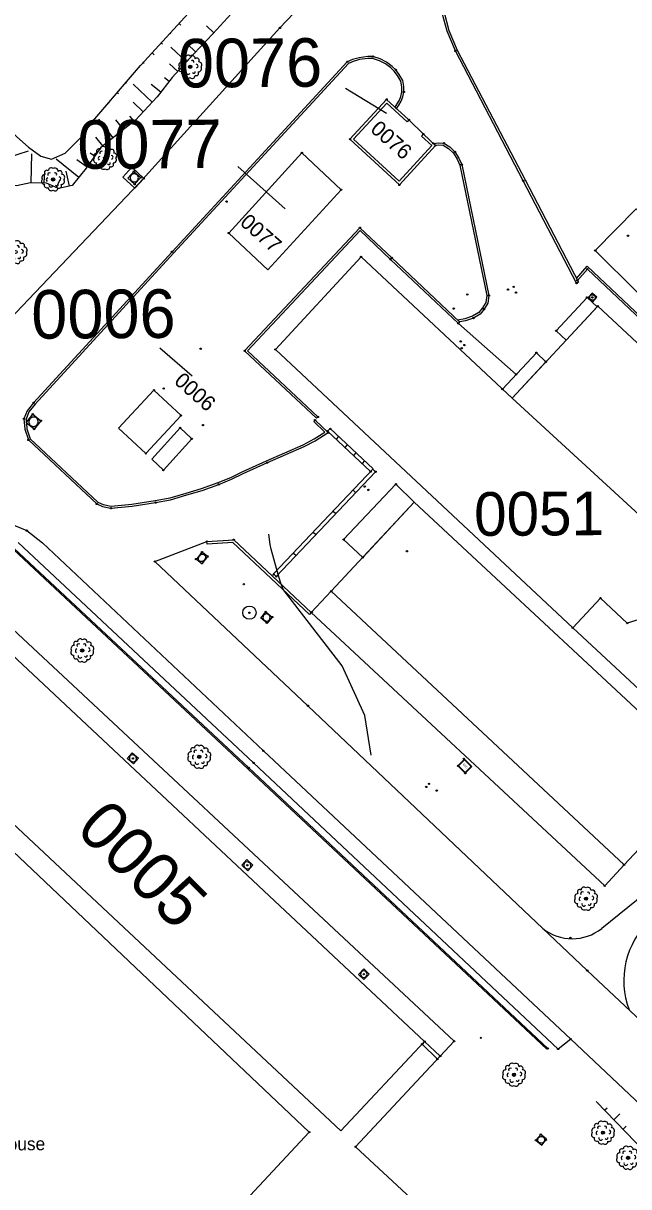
# Model space of a CAD drawing. Extents: x 344013 to 344423, y 298505 to 298795.
# Drawn here: x 344176.7 to 344222.4, y 298618.3 to 298706.1 of the extents above; entities that cross this region are included whole.
import ezdxf

# ---------------------------------------------------------------- set-up
doc = ezdxf.new("R2010")
doc.units = 0
for name, color, linetype in [('Default', 7, 'Continuous'), ('DH_CADRE -CARTOUCHE', 7, 'Continuous'), ('GO_MUR', 7, 'Continuous'), ('PC_CONCRETE', 7, 'Continuous'), ('PS_BOLT', 7, 'Continuous'), ('PS_CONST', 7, 'Continuous'), ('PS_HIDDEN', 7, 'Continuous'), ('PS_SOLID', 7, 'Continuous'), ('RES_ELECTRICITE', 7, 'Continuous'), ('TOPO_POINT', 7, 'Continuous'), ('TOPO_TALUS-TERRAIN NATUREL', 7, 'Continuous'), ('VOIRIE_BORDURE', 7, 'Continuous'), ('VOIRIE_ESPACE VERT', 7, 'Continuous')]:
    doc.layers.add(name, color=color, linetype=linetype)

# ---------------------------------------------------------------- blocks, each defined once
blk = doc.blocks.new('REG_INC')
at = {"layer": 'Default'}
for p, q in [((0, 1), (1, 1)), ((0, 0), (0, 1)), ((1, 0), (0, 0)), ((1, 1), (1, 0))]:
    blk.add_line(p, q, dxfattribs=at)
for start, end in [(135.0055, 180.0055), (180.0066, 225.0066), (90.0058, 135.0058), (225.0069, 270.0069), (45.0069, 90.0069), (270.0058, 315.0058), (0.0066, 45.0066), (315.0055, 0.0055)]:
    blk.add_arc((0.5, 0.5), 0.44, start, end, dxfattribs=at)
blk = doc.blocks.new('R5')
at = {"layer": 'Default'}
for p, q in [((0, 1), (0, 0)), ((1, 1), (0, 1)), ((0.2, 1), (0.2, 0)), ((0.4, 1), (0.4, 0)), ((0.6, 1), (0.6, 0)), ((0.8, 1), (0.8, 0)), ((1, 0), (1, 1)), ((0, 0), (1, 0)), ((0.6, 0), (0.6, 0))]:
    blk.add_line(p, q, dxfattribs=at)
blk = doc.blocks.new('RES_ELECTRICITE')
at = {"layer": 'RES_ELECTRICITE'}
for points in [[(0, 0), (0, 1), (1, 1), (1, 0)], [(0.05, 0.05), (0.05, 0.95), (0.95, 0.95), (0.95, 0.05)]]:
    blk.add_lwpolyline(points, close=True, dxfattribs=at)
blk.add_text('EEC', height=0.2, dxfattribs=at).set_placement((0.24, 0.46))
blk = doc.blocks.new('POINT_DISPLAY')
at = {"layer": 'Default'}
blk.add_circle((0, 0), 0.05, dxfattribs=at)
blk = doc.blocks.new('ARB1')
at = {"layer": 'Default'}
blk.add_circle((0, 0), 0.122, dxfattribs=at)
for centre, radius, start, end in [((-0.613, 0.139), 0.241, 88.45835, 215.19284), ((-0.471, 0.503), 0.183, 53.95544, 222.20655), ((-0.373, -0.024), 0.149, 103.70924, 242.34652), ((-0.276, 0.37), 0.134, 52.43963, 209.54959), ((-0.153, 0.664), 0.211, 43.69255, 183.5969), ((0.139, 0.613), 0.241, 358.45835, 125.19284), ((0.164, 0.38), 0.112, 330.58954, 133.71274), ((0.501, 0.468), 0.183, 325.14445, 131.01755), ((0.458, 0.052), 0.137, 276.62143, 88.96702), ((0.613, -0.139), 0.241, 268.45835, 35.19284), ((0.664, 0.153), 0.211, 313.69255, 93.5969), ((-0.664, -0.153), 0.211, 133.69255, 273.5969), ((-0.478, -0.443), 0.19, 155.22426, 300.93774), ((-0.139, -0.613), 0.241, 178.45835, 305.19284), ((-0.163, -0.42), 0.148, 159.53711, 338.16632), ((0.153, -0.664), 0.211, 223.69255, 3.5969), ((0.271, -0.38), 0.112, 210.58954, 13.71274), ((0.448, -0.483), 0.188, 243.13234, 33.02965)]:
    blk.add_arc(centre, radius, start, end, dxfattribs=at)

msp = doc.modelspace()

# ---------------------------------------------------------------- linework, layer by layer
at = {"layer": 'DH_CADRE -CARTOUCHE'}
msp.add_lwpolyline([(344227.517, 298664.97), (344227.114, 298664.539), (344225.446, 298664.062), (344226.044, 298661.968), (344222.259, 298660.802), (344220.242, 298662.699), (344218.145, 298660.448), (344195.697, 298681.448), (344202.162, 298688.436), (344213.563, 298677.785), (344227.517, 298664.97)], dxfattribs=at)
for points in [[(344213.563, 298677.785), (344235.857, 298657.311), (344242.178, 298664.083), (344220.032, 298684.709)], [(344206.167, 298669.932), (344199.92, 298663.204), (344222.021, 298642.559), (344228.339, 298649.299)], [(344200.65, 298622.487), (344165.426, 298655.454), (344171.721, 298662.233), (344206.962, 298629.231)]]:
    msp.add_lwpolyline(points, close=True, dxfattribs=at)
at = {"layer": 'GO_MUR'}
for points in [[(344205.78, 298698.773), (344205.645, 298698.626), (344204.106, 298700.035), (344201.605, 298697.33), (344205.052, 298694.149), (344207.504, 298696.841), (344206.737, 298697.554), (344206.873, 298697.701), (344207.785, 298696.853), (344205.064, 298693.865), (344201.322, 298697.318), (344204.095, 298700.317)], [(344201.322, 298697.318), (344205.064, 298693.865), (344207.785, 298696.853), (344206.873, 298697.701), (344205.78, 298698.773), (344204.095, 298700.317)], [(344204.49, 298688.357), (344202.08, 298690.635), (344193.372, 298681.35), (344198.801, 298676.258), (344198.91, 298676.36), (344193.587, 298681.359), (344202.087, 298690.422), (344204.387, 298688.248)], [(344190.525, 298666.955), (344192.555, 298667.101), (344198.399, 298661.611), (344198.262, 298661.465), (344192.482, 298666.895), (344190.539, 298666.755)]]:
    msp.add_lwpolyline(points, close=True, dxfattribs=at)
for points in [[(344162.931, 298666.015), (344158.413, 298661.325), (344158.342, 298661.39), (344163.216, 298666.766), (344163.731, 298667.308), (344164.688, 298668.072), (344165.676, 298668.545), (344166.447, 298668.825), (344167.222, 298669.059), (344168.509, 298669.289), (344169.751, 298669.392), (344170.251, 298669.414), (344170.803, 298669.375), (344172.06, 298669.227), (344173.884, 298668.877), (344175.641, 298668.318), (344176.928, 298667.79), (344178.107, 298666.872), (344194.798, 298651.17), (344217.989, 298629.411), (344217.037, 298628.671)], [(344217.037, 298628.671), (344194.049, 298650.256), (344176.274, 298666.89)], [(344175.978, 298666.428), (344193.686, 298649.877), (344216.254, 298628.72), (344216.185, 298628.648), (344193.618, 298649.804), (344175.917, 298666.349)]]:
    msp.add_lwpolyline(points, dxfattribs=at)
msp.add_circle((344193.735, 298661.592), 0.5, dxfattribs=at)
at = {"layer": 'PS_BOLT'}
for points in [[(344184.871, 298695.2), (344185.767, 298694.36), (344185.084, 298693.618), (344184.188, 298694.458)], [(344222.928, 298692.059), (344219.848, 298688.907), (344223.024, 298685.745), (344226.701, 298689.518), (344224.975, 298691.361), (344224.35, 298690.749)], [(344186.526, 298678.381), (344188.581, 298676.471), (344185.918, 298673.601), (344183.863, 298675.512)], [(344188.509, 298675.532), (344189.384, 298674.705), (344187.243, 298672.345), (344186.368, 298673.172)], [(344199.92, 298663.204), (344198.399, 298661.611), (344220.56, 298640.98), (344222.021, 298642.559)]]:
    msp.add_lwpolyline(points, close=True, dxfattribs=at)
for points in [[(344209.51, 298683.413), (344213.876, 298679.574)], [(344173.637, 298593.851), (344172.292, 298595.161), (344185.567, 298608.8), (344198.259, 298622.397), (344163.217, 298655.561), (344163.898, 298656.291), (344171.693, 298664.218), (344209.192, 298629.258), (344201.744, 298621.299), (344205.95, 298617.379), (344203.771, 298607.721), (344197.46, 298609.156), (344192.341, 298613.899), (344190.988, 298612.393), (344196.963, 298606.8), (344195.985, 298605.701)], [(344208.14, 298628.134), (344206.962, 298629.231), (344206.772, 298629.027), (344207.928, 298627.907)]]:
    msp.add_lwpolyline(points, dxfattribs=at)
at = {"layer": 'PS_CONST'}
for p, q in [((344200.988, 298701.17), (344204.075, 298699.283)), ((344192.865, 298695.267), (344196.437, 298692.051)), ((344186.963, 298681.569), (344189.41, 298679.451))]:
    msp.add_line(p, q, dxfattribs=at)
at = {"layer": 'PS_HIDDEN'}
for points in [[(344219.222, 298685.379), (344219.989, 298684.663), (344217.654, 298682.164), (344216.904, 298682.865), (344219.222, 298685.379)], [(344215.399, 298681.203), (344216.124, 298680.526), (344213.563, 298677.785), (344212.838, 298678.462), (344215.399, 298681.203)], [(344226.423, 298664.341), (344232.564, 298658.67), (344226.766, 298652.449), (344218.145, 298660.448)]]:
    msp.add_lwpolyline(points, dxfattribs=at)
msp.add_lwpolyline([(344202.301, 298665.744), (344200.842, 298667.111), (344204.795, 298671.279), (344206.167, 298669.932)], close=True, dxfattribs=at)
at = {"layer": 'PS_SOLID'}
msp.add_lwpolyline([(344200.665, 298693.504), (344197.698, 298696.276), (344192.173, 298690.236), (344195.14, 298687.464)], close=True, dxfattribs=at)
at = {"layer": 'TOPO_TALUS-TERRAIN NATUREL'}
for p, q in [((344188.428, 298706.05), (344188.558, 298705.93)), ((344191.06, 298705.342), (344190.495, 298705.862)), ((344187.75, 298705.314), (344187.806, 298705.263)), ((344190.369, 298704.619), (344190.077, 298704.899)), ((344186.395, 298703.842), (344186.558, 298703.692)), ((344187.073, 298704.578), (344187.168, 298704.49)), ((344188.997, 298703.163), (344187.806, 298704.254)), ((344189.676, 298703.898), (344189.061, 298704.488)), ((344185.717, 298703.107), (344185.787, 298703.043)), ((344188.321, 298702.426), (344187.694, 298703)), ((344185.06, 298702.353), (344185.091, 298702.327)), ((344184.411, 298701.592), (344184.464, 298701.547)), ((344186.406, 298700.119), (344184.954, 298701.472)), ((344187.057, 298700.877), (344186.311, 298701.454)), ((344187.669, 298701.668), (344187.315, 298701.942)), ((344183.762, 298700.83), (344183.852, 298700.754)), ((344183.114, 298700.069), (344183.152, 298700.036)), ((344185.725, 298699.387), (344184.96, 298700.099)), ((344181.816, 298698.546), (344181.844, 298698.522)), ((344183.458, 298697.431), (344182.361, 298698.833)), ((344182.465, 298699.308), (344182.481, 298699.294)), ((344184.244, 298698.049), (344183.66, 298698.785)), ((344185.028, 298698.671), (344184.72, 298699.059)), ((344182.67, 298696.815), (344182.15, 298697.479)), ((344174.22, 298695.529), (344177.051, 298696.448)), ((344177.249, 298694.03), (344177.324, 298696.208)), ((344180.856, 298694.434), (344179.157, 298695.812)), ((344182.055, 298696.034), (344181.728, 298696.264)), ((344181.481, 298695.215), (344180.715, 298695.752)), ((344178.249, 298693.996), (344178.281, 298694.927)), ((344179.184, 298693.667), (344179.445, 298694.288)), ((344180.152, 298693.778), (344179.912, 298694.904)), ((344220.55, 298624.054), (344220.742, 298624.239)), ((344221.245, 298623.334), (344221.695, 298623.769)), ((344221.94, 298622.615), (344222.178, 298622.844))]:
    msp.add_line(p, q, dxfattribs=at)
for points in [[(344148.445, 298717.676), (344150.54, 298719.466), (344152.414, 298719.731), (344154.52, 298718.736), (344157.154, 298716.789), (344159.618, 298714.441), (344161.857, 298712.179), (344163.938, 298709.792), (344165.996, 298707.602), (344168.133, 298705.364), (344169.649, 298703.764), (344171.689, 298701.731), (344173.402, 298700.124), (344174.981, 298698.62), (344176.175, 298697.484), (344177.055, 298696.727), (344177.983, 298696.033), (344178.792, 298695.819), (344179.816, 298696.274), (344181.06, 298697.498), (344181.167, 298697.785)], [(344192.371, 298706.767), (344190.985, 298705.261), (344189.552, 298703.768), (344187.895, 298701.96), (344186.776, 298700.516), (344185.144, 298698.764), (344183.988, 298697.846), (344182.522, 298696.699), (344181.424, 298695.135), (344180.359, 298693.822), (344179.336, 298693.603), (344178.417, 298693.99), (344177.213, 298694.032), (344176.166, 298693.805), (344175.237, 298693.885), (344174.421, 298694.91), (344173.943, 298696.382), (344173.127, 298697.863), (344171.784, 298699.194), (344169.649, 298701.006), (344167.952, 298702.614), (344166.263, 298704.166), (344164.386, 298705.861), (344162.327, 298707.753)], [(344181.167, 298697.785), (344185.518, 298702.89), (344189.41, 298707.116)], [(344202.925, 298650.83), (344202.457, 298653.824), (344200.73, 298657.577), (344196.307, 298663.307), (344196.174, 298663.613), (344196.088, 298663.905), (344195.908, 298664.48), (344195.376, 298666.385), (344195.306, 298666.724), (344195.213, 298667.526)], [(344227.328, 298617.038), (344219.907, 298624.72)]]:
    msp.add_lwpolyline(points, dxfattribs=at)
at = {"layer": 'VOIRIE_BORDURE'}
for points in [[(344128.542, 298697.099), (344156.76, 298672.229), (344158.923, 298671.699), (344160.816, 298671.605), (344163.478, 298672.279), (344165.611, 298673.484), (344167.1, 298674.65), (344168.229, 298675.97), (344185.426, 298693.989), (344196.039, 298705.71), (344211.949, 298722.43)], [(344218.437, 298686.461), (344214.412, 298694.17), (344209.291, 298703.973), (344208.659, 298705.478), (344208.291, 298706.838), (344207.976, 298708.478), (344207.839, 298709.863), (344207.906, 298710.324), (344208.098, 298710.832), (344215.814, 298719.252), (344216.198, 298719.615), (344216.729, 298720.015), (344217.376, 298720.272), (344218.071, 298720.41), (344218.955, 298720.246), (344219.71, 298719.9), (344220.275, 298719.385), (344221.201, 298718.398)], [(344221.201, 298718.398), (344221.092, 298718.296), (344220.17, 298719.278), (344219.626, 298719.773), (344218.909, 298720.102), (344218.072, 298720.258), (344217.419, 298720.128), (344216.803, 298719.883), (344216.295, 298719.5), (344215.921, 298719.147), (344208.228, 298710.752), (344208.052, 298710.286), (344207.99, 298709.86), (344208.125, 298708.5), (344208.437, 298706.871), (344208.801, 298705.527), (344209.426, 298704.037), (344214.545, 298694.239), (344218.57, 298686.531), (344218.437, 298686.461)], [(344204.84, 298699.634), (344205.028, 298699.895), (344205.198, 298700.193), (344205.312, 298700.507), (344205.406, 298700.884), (344205.39, 298701.29), (344205.308, 298701.744), (344205.047, 298702.198), (344204.788, 298702.553), (344204.513, 298702.809), (344204.082, 298703.135), (344203.608, 298703.371), (344203.064, 298703.553), (344202.667, 298703.549), (344202.019, 298703.466), (344201.522, 298703.323), (344201.126, 298703.152), (344187.902, 298688.824), (344177.441, 298677.433), (344176.96, 298676.824), (344176.719, 298676.211), (344176.783, 298675.437), (344177.049, 298674.626), (344182.208, 298669.797), (344182.64, 298669.601), (344183.285, 298669.47), (344184.88, 298669.638), (344186.656, 298669.899), (344187.783, 298670.119), (344189.007, 298670.475), (344190.164, 298670.82), (344191.42, 298671.271), (344192.391, 298671.666), (344193.259, 298672.085), (344195.097, 298672.911), (344197.862, 298674.128), (344198.708, 298674.569), (344199.685, 298675.181), (344198.697, 298676.128)], [(344204.729, 298699.736), (344204.902, 298699.977), (344205.061, 298700.256), (344205.168, 298700.551), (344205.255, 298700.899), (344205.24, 298701.273), (344205.165, 298701.692), (344204.921, 298702.116), (344204.675, 298702.453), (344204.416, 298702.694), (344204.003, 298703.007), (344203.55, 298703.232), (344203.04, 298703.403), (344202.677, 298703.399), (344202.05, 298703.318), (344201.572, 298703.181), (344201.215, 298703.026), (344188.012, 298688.722), (344177.555, 298677.336), (344177.092, 298676.749), (344176.872, 298676.188), (344176.931, 298675.467), (344177.18, 298674.709), (344182.292, 298669.924), (344182.687, 298669.745), (344183.293, 298669.621), (344184.862, 298669.787), (344186.631, 298670.046), (344187.747, 298670.264), (344188.964, 298670.619), (344190.117, 298670.962), (344191.366, 298671.411), (344192.331, 298671.803), (344193.196, 298672.221), (344195.036, 298673.048), (344197.797, 298674.263), (344198.633, 298674.699), (344199.442, 298675.206), (344198.593, 298676.019), (344198.697, 298676.128)], [(344207.629, 298696.998), (344207.977, 298697.048), (344208.425, 298697.015), (344208.872, 298696.729), (344209.25, 298696.353), (344209.554, 298695.892), (344209.763, 298695.4), (344211.822, 298685.518), (344211.725, 298684.944), (344211.452, 298684.497), (344211.149, 298684.116), (344210.642, 298683.824), (344210.048, 298683.612), (344209.602, 298683.532)], [(344207.77, 298696.867), (344207.983, 298696.898), (344208.376, 298696.868), (344208.778, 298696.612), (344209.133, 298696.258), (344209.422, 298695.821), (344209.619, 298695.355), (344211.669, 298685.515), (344211.582, 298684.997), (344211.329, 298684.583), (344211.049, 298684.232), (344210.578, 298683.961), (344210.009, 298683.757), (344209.466, 298683.66)], [(344204.387, 298688.248), (344209.51, 298683.413)], [(344204.49, 298688.357), (344209.602, 298683.532)], [(344218.426, 298686.806), (344219.242, 298687.726), (344227.876, 298679.586), (344229.255, 298681.159), (344230.281, 298680.25)], [(344218.501, 298686.664), (344219.252, 298687.511), (344227.886, 298679.371), (344229.269, 298680.947), (344230.182, 298680.138)], [(344209.602, 298683.532), (344209.51, 298683.413)], [(344120.412, 298621.951), (344137.791, 298639.981), (344144.065, 298646.663), (344154.783, 298657.656), (344157.662, 298660.576), (344158.342, 298661.39), (344163.216, 298666.766), (344163.731, 298667.308), (344164.688, 298668.072), (344165.676, 298668.545), (344166.447, 298668.825), (344167.222, 298669.059), (344168.509, 298669.289), (344169.751, 298669.392), (344170.251, 298669.414), (344170.803, 298669.375), (344172.06, 298669.227), (344173.884, 298668.877), (344175.641, 298668.318), (344176.928, 298667.79), (344178.107, 298666.872), (344194.798, 298651.17), (344217.989, 298629.411), (344240.944, 298607.781)], [(344186.596, 298665.445), (344190.525, 298666.955)], [(344253.72, 298623.882), (344254.601, 298622.951), (344255.115, 298621.851), (344255.304, 298620.858), (344255.289, 298620.014), (344254.937, 298619.35), (344253.379, 298617.242), (344250.056, 298613.162), (344249.016, 298611.996), (344247.858, 298610.985), (344246.303, 298610.451), (344244.928, 298610.512), (344219.242, 298634.584), (344198.152, 298654.571), (344186.596, 298665.445)], [(344223.61, 298640.396), (344220.335, 298637.772)]]:
    msp.add_lwpolyline(points, dxfattribs=at)
for centre, radius, start, end in [((344228.199, 298633.832), 6.201, 132.57867, 200.9263), ((344218.106, 298640.554), 3.565, 231.25262, 308.69595)]:
    msp.add_arc(centre, radius, start, end, dxfattribs=at)

# ---------------------------------------------------------------- block references
at = {"layer": 'PC_CONCRETE'}
for name, p, xscale, yscale, rotation in [('REG_INC', (344185.072, 298693.912), 0.69360313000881, 0.6911557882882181, 47.961450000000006), ('REG_INC', (344219.601, 298685.712), 0.4871224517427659, -0.45832881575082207, -41.48739000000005), ('REG_INC', (344178.003, 298676.077), 0.7870153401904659, 0.8167466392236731, 141.88994999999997), ('R5', (344199.63, 298675.281), 4.461995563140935, 0.281758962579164, -43.07112000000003), ('R5', (344195.759, 298664.32), 10.90436902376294, 0.277187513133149, 46.491209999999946), ('REG_INC', (344190.157, 298666.166), 0.544789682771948, -0.693485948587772, -37.86570000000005), ('REG_INC', (344195.459, 298661.265), 0.6254069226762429, 0.600478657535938, 141.24761999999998), ('REG_INC', (344184.895, 298651.021), 0.570230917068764, 0.631212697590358, -131.48361), ('REG_INC', (344193.53, 298642.959), 0.570230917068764, 0.631212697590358, -131.48361), ('REG_INC', (344202.369, 298634.717), 0.5772372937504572, 0.562669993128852, -133.64937), ('REG_INC', (344215.364, 298621.784), 0.569802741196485, -0.570461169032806, 50.268059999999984)]:
    msp.add_blockref(name, p, dxfattribs=dict(at, xscale=xscale, yscale=yscale, rotation=rotation))
at = {"layer": 'RES_ELECTRICITE', "xscale": 0.790873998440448, "yscale": 0.7059396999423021, "rotation": -45.06567324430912}
msp.add_blockref('RES_ELECTRICITE', (344209.47, 298650.035), dxfattribs=at)
at = {"layer": 'TOPO_POINT'}
for p in [(344196.039, 298705.71), (344209.291, 298703.973), (344201.126, 298703.152), (344203.064, 298703.553), (344189.269, 298702.78), (344204.788, 298702.553), (344204.095, 298700.317), (344205.406, 298700.884), (344204.84, 298699.634), (344205.78, 298698.773), (344206.873, 298697.701), (344201.322, 298697.318), (344207.629, 298696.998), (344207.785, 298696.853), (344208.425, 298697.015), (344182.845, 298695.901), (344197.698, 298696.276), (344209.25, 298696.353), (344184.871, 298695.2), (344185.02, 298694.887), (344209.763, 298695.4), (344178.918, 298694.284), (344185.537, 298694.428), (344185.767, 298694.36), (344214.412, 298694.17), (344185.072, 298693.912), (344200.665, 298693.504), (344205.064, 298693.865), (344192.019, 298692.611), (344202.08, 298690.635), (344192.173, 298690.236), (344222.313, 298690.029), (344187.902, 298688.824), (344219.848, 298688.907), (344202.162, 298688.436), (344204.387, 298688.248), (344204.49, 298688.357), (344219.252, 298687.511), (344213.689, 298686.178), (344218.437, 298686.461), (344218.501, 298686.664), (344210.181, 298685.597), (344211.822, 298685.518), (344213.249, 298685.972), (344213.852, 298685.747), (344219.222, 298685.379), (344219.632, 298685.378), (344209.16, 298684.535), (344211.452, 298684.497), (344220.032, 298684.709), (344210.642, 298683.824), (344209.51, 298683.413), (344216.904, 298682.865), (344209.685, 298682.064), (344209.966, 298681.782), (344190.065, 298681.504), (344193.372, 298681.35), (344195.697, 298681.448), (344209.761, 298681.538), (344215.399, 298681.203), (344216.124, 298680.526), (344213.876, 298679.574), (344186.526, 298678.381), (344187.264, 298678.509), (344212.838, 298678.462), (344177.441, 298677.433), (344177.384, 298676.563), (344188.581, 298676.471), (344176.719, 298676.211), (344178.003, 298676.077), (344190.231, 298675.746), (344198.697, 298676.128), (344198.91, 298676.36), (344177.488, 298675.443), (344188.509, 298675.532), (344189.384, 298674.705), (344199.63, 298675.281), (344199.685, 298675.181), (344199.847, 298675.465), (344177.049, 298674.626), (344185.918, 298673.601), (344187.243, 298672.345), (344195.097, 298672.911), (344202.89, 298672.234), (344203.266, 298672.228), (344191.42, 298671.271), (344204.795, 298671.279), (344202.442, 298671.11), (344202.721, 298670.851), (344182.208, 298669.797), (344183.285, 298669.47), (344186.656, 298669.899), (344176.928, 298667.79), (344190.525, 298666.955), (344192.555, 298667.101), (344200.842, 298667.111), (344190.157, 298666.166), (344205.628, 298666.228), (344186.596, 298665.445), (344189.708, 298665.637), (344190.587, 298665.832), (344202.301, 298665.744), (344195.56, 298664.474), (344195.759, 298664.32), (344193.314, 298663.734), (344199.92, 298663.204), (344220.242, 298662.699), (344193.735, 298661.592), (344194.971, 298661.657), (344198.399, 298661.611), (344198.447, 298661.622), (344195.043, 298660.83), (344195.459, 298661.265), (344222.259, 298660.802), (344218.145, 298660.448), (344181.12, 298658.739), (344198.152, 298654.571), (344194.798, 298651.17), (344184.942, 298650.6), (344189.95, 298650.719), (344194.049, 298650.256), (344209.922, 298650.576), (344193.686, 298649.877), (344209.47, 298650.035), (344210.028, 298649.475), (344207.089, 298648.441), (344207.294, 298648.679), (344207.879, 298648.172), (344193.578, 298642.536), (344222.021, 298642.559), (344220.56, 298640.98), (344219.146, 298640.016), (344217.964, 298637.053), (344202.373, 298634.314), (344219.242, 298634.584), (344206.962, 298629.231), (344209.192, 298629.258), (344211.205, 298629.513), (344217.989, 298629.411), (344206.772, 298629.027), (344216.254, 298628.72), (344217.037, 298628.671), (344207.928, 298627.907), (344208.14, 298628.134), (344213.711, 298626.73), (344198.259, 298622.397), (344215.729, 298622.222), (344220.426, 298622.356), (344201.744, 298621.299), (344215.364, 298621.784), (344216.133, 298621.817), (344222.322, 298620.459)]:
    msp.add_blockref('POINT_DISPLAY', p, dxfattribs=at)
at = {"layer": 'VOIRIE_ESPACE VERT'}
for p in [(344189.269, 298702.78), (344182.845, 298695.901), (344178.918, 298694.284), (344176.083, 298688.804), (344181.12, 298658.739), (344189.95, 298650.719), (344219.146, 298640.016), (344213.711, 298626.73), (344220.426, 298622.356), (344222.322, 298620.459)]:
    msp.add_blockref('ARB1', p, dxfattribs=at)

# ---------------------------------------------------------------- texts
at = {"layer": 'PS_CONST'}
for s, height, rotation, p in [('0076', 3.662, 0.3665, (344188.349, 298701.214)), ('0077', 3.662, 0.3665, (344180.755, 298695.075)), ('0076', 1.1492, 318.61911, (344202.796, 298697.96)), ('0077', 1.1492, 318.61911, (344192.953, 298690.924)), ('0006', 3.662, 0.3665, (344177.282, 298682.264)), ('0006', 1.1492, 318.61911, (344187.983, 298678.958)), ('0051', 3.2958, 0.3665, (344210.709, 298667.383)), ('0005', 3.662, 315.36651, (344180.527, 298645.151)), ('Pelouse', 0.9758, 0.36652, (344173.608, 298621.005))]:
    msp.add_text(s, height=height, rotation=rotation, dxfattribs=at).set_placement(p)

doc.saveas('drawing.dxf')
